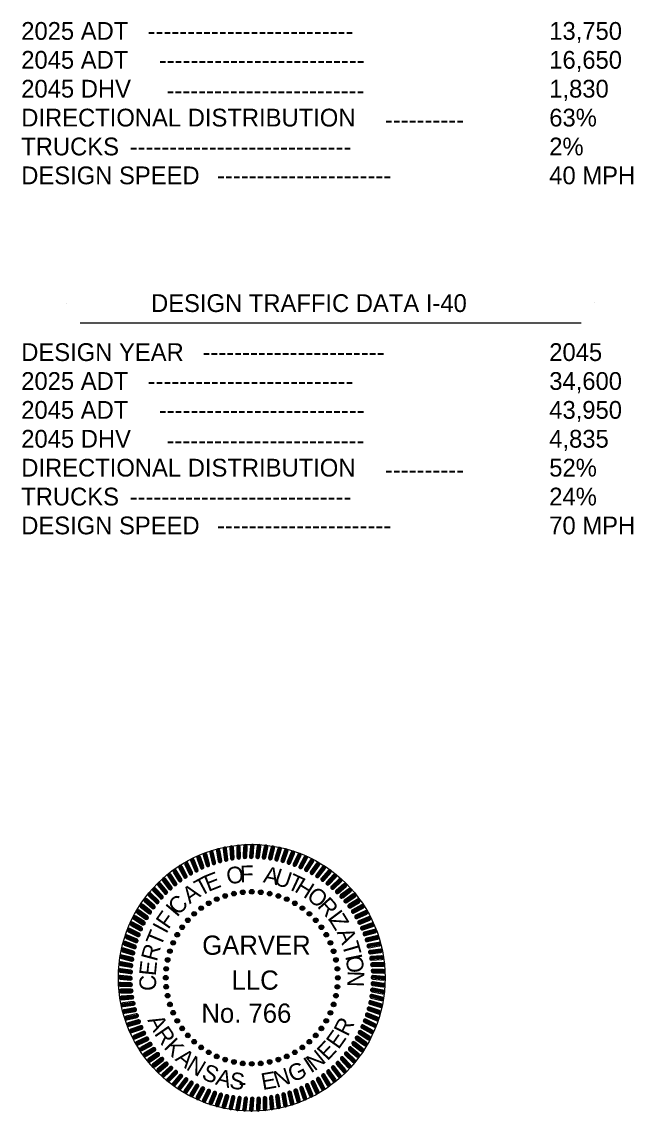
# Model space of a CAD drawing. Extents: x 535214 to 694517, y 381272 to 484355.
# Drawn here: x 658244 to 685754, y 383251 to 432276 of the extents above; entities that cross this region are included whole.
import ezdxf

# ---------------------------------------------------------------- set-up
doc = ezdxf.new("R2010")
doc.units = 0
for name, color, linetype in [('1', 7, 'Continuous'), ('2', 7, 'Continuous'), ('G-ANNO-STMP', 7, 'Continuous'), ('G-ANNO-TEXT', 7, 'Continuous')]:
    doc.layers.add(name, color=color, linetype=linetype)

# ---------------------------------------------------------------- blocks, each defined once
blk = doc.blocks.new('SEALDO')
at = {"layer": 'G-ANNO-TEXT'}
for radius in [0.0396, 0.0305, 0.0213, 0.0122, 0.00305]:
    blk.add_circle((1.403, -0.456), radius, dxfattribs=at)
blk = doc.blocks.new('SEALRI')
at = {"layer": 'G-ANNO-TEXT'}
for p, q in [((-0.023, 2.258), (-0.038, 2.081)), ((-0.008, 2.281), (-0.028, 2.056)), ((0.004, 2.286), (-0.016, 2.049)), ((0.016, 2.285), (-0.004, 2.048)), ((0.028, 2.278), (0.008, 2.052)), ((0.023, 2.076), (0.038, 2.253))]:
    blk.add_line(p, q, dxfattribs=at)
for centre, start, end in [((0.008, 2.256), 355, 175), ((-0.008, 2.078), 175, 355)]:
    blk.add_arc(centre, 0.0305, start, end, dxfattribs=at)

msp = doc.modelspace()

# ---------------------------------------------------------------- linework, layer by layer
at = {"layer": '1'}
for p, q in [((660254, 419616), (660254, 419616)), ((684029, 419646), (684029, 419646)), ((660875, 418727), (683419, 418727))]:
    msp.add_line(p, q, dxfattribs=at)
at = {"layer": 'G-ANNO-STMP'}
msp.add_circle((668592, 389255), 6000, dxfattribs=at)
msp.add_circle((668592, 389255), 6000, dxfattribs=at)

# ---------------------------------------------------------------- block references
for name, xscale, yscale, rotation in [('SEALRI', 2624.6202983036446, 2624.6202983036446, 12.000000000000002), ('SEALRI', 2624.6202983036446, 2624.6202983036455, 9), ('SEALRI', 2624.6202983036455, 2624.6202983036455, 6), ('SEALRI', 2624.620298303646, 2624.6202983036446, 3), ('SEALRI', 2624.6202983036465, 2624.620298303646, -2.999999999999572), ('SEALRI', 2624.620298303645, 2624.6202983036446, -5.9999999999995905), ('SEALRI', 2624.620298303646, 2624.6202983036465, -8.999999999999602), ('SEALRI', 2624.6202983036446, 2624.620298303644, -11.999999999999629), ('SEALRI', 2624.6202983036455, 2624.6202983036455, 26.999999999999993), ('SEALRI', 2624.6202983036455, 2624.6202983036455, 23.999999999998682), ('SEALRI', 2624.6202983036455, 2624.6202983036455, 20.999999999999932), ('SEALRI', 2624.6202983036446, 2624.6202983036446, 18), ('SEALRI', 2624.620298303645, 2624.620298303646, 15.000000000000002), ('SEALRI', 2624.620298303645, 2624.620298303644, -14.99999999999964), ('SEALRI', 2624.620298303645, 2624.620298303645, -17.999999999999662), ('SEALRI', 2624.620298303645, 2624.6202983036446, -20.999999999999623), ('SEALRI', 2624.620298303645, 2624.620298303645, -23.99999999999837), ('SEALRI', 2624.6202983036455, 2624.620298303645, -26.999999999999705), ('SEALRI', 2624.620298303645, 2624.6202983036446, 36), ('SEALRI', 2624.620298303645, 2624.6202983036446, 33), ('SEALRI', 2624.620298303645, 2624.6202983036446, 30.00000000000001), ('SEALRI', 2624.6202983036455, 2624.6202983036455, -29.99999999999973), ('SEALRI', 2624.6202983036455, 2624.620298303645, -32.999999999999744), ('SEALRI', 2624.620298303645, 2624.6202983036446, -35.999999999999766), ('SEALRI', 2624.6202983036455, 2624.6202983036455, 41.999999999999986), ('SEALRI', 2624.620298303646, 2624.620298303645, 38.999999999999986), ('SEALRI', 2624.620298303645, 2624.620298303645, -38.999999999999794), ('SEALRI', 2624.620298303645, 2624.620298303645, -41.99999999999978), ('SEALRI', 2624.6202983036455, 2624.6202983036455, 47.99999999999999), ('SEALRI', 2624.6202983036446, 2624.620298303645, 44.999999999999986), ('SEALDO', 2624.6202983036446, 2624.620298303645, 119.99999999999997), ('SEALDO', 2624.620298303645, 2624.6202983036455, 113.99999999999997), ('SEALDO', 2624.620298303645, 2624.620298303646, 107.99999999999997), ('SEALDO', 2624.620298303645, 2624.620298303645, 101.99999999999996), ('SEALRI', 2624.620298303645, 2624.620298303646, -44.99999999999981), ('SEALRI', 2624.6202983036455, 2624.6202983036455, -47.99999999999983), ('SEALRI', 2624.620298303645, 2624.6202983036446, 54), ('SEALRI', 2624.620298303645, 2624.620298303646, 51), ('SEALDO', 2624.620298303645, 2624.620298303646, 138), ('SEALDO', 2624.620298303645, 2624.6202983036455, 131.99999999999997), ('SEALDO', 2624.6202983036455, 2624.6202983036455, 125.99999999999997), ('SEALDO', 2624.6202983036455, 2624.6202983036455, 95.99999999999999), ('SEALDO', 2624.6202983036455, 2624.6202983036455, 90), ('SEALDO', 2624.6202983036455, 2624.620298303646, 83.99999999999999), ('SEALDO', 2624.6202983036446, 2624.620298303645, 77.99999999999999), ('SEALRI', 2624.620298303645, 2624.6202983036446, -50.999999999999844), ('SEALRI', 2624.620298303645, 2624.6202983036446, -53.999999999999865), ('SEALRI', 2624.6202983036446, 2624.6202983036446, 59.999999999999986), ('SEALRI', 2624.620298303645, 2624.620298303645, 56.99999999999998), ('SEALDO', 2624.620298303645, 2624.6202983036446, 150), ('SEALDO', 2624.6202983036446, 2624.620298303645, 144), ('SEALDO', 2624.6202983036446, 2624.620298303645, 72), ('SEALDO', 2624.6202983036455, 2624.6202983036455, 66.00000000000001), ('SEALRI', 2624.620298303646, 2624.620298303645, -56.999999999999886), ('SEALRI', 2624.620298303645, 2624.6202983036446, -59.99999999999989), ('SEALRI', 2624.620298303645, 2624.6202983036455, 65.99999999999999), ('SEALRI', 2624.6202983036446, 2624.6202983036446, 63), ('SEALDO', 2624.6202983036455, 2624.6202983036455, 156.00000000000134), ('SEALDO', 2624.620298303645, 2624.6202983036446, 60.00000000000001), ('SEALRI', 2624.6202983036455, 2624.6202983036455, -62.99999999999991), ('SEALRI', 2624.6202983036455, 2624.620298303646, -65.99999999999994), ('SEALRI', 2624.6202983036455, 2624.6202983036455, 68.99999999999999), ('SEALDO', 2624.620298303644, 2624.6202983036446, 168.00000000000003), ('SEALDO', 2624.6202983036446, 2624.620298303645, 162.00000000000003), ('SEALDO', 2624.620298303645, 2624.6202983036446, 54), ('SEALDO', 2624.6202983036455, 2624.6202983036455, 48.00000000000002), ('SEALRI', 2624.620298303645, 2624.6202983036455, -68.99999999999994), ('SEALRI', 2624.620298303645, 2624.620298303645, 75.00000000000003), ('SEALRI', 2624.6202983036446, 2624.620298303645, 72), ('SEALDO', 2624.6202983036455, 2624.6202983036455, 174.00000000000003), ('SEALDO', 2624.6202983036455, 2624.6202983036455, 42.000000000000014), ('SEALRI', 2624.620298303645, 2624.6202983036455, -71.99999999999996), ('SEALRI', 2624.6202983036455, 2624.6202983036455, -74.99999999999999), ('SEALRI', 2624.6202983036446, 2624.6202983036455, 81), ('SEALRI', 2624.6202983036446, 2624.6202983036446, 78.00000000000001), ('SEALDO', 2624.6202983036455, 2624.6202983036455, -179.99999999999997), ('SEALDO', 2624.620298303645, 2624.6202983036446, 36), ('SEALRI', 2624.6202983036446, 2624.6202983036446, -78), ('SEALRI', 2624.6202983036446, 2624.620298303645, -81.00000000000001), ('SEALRI', 2624.6202983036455, 2624.6202983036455, 84.00000000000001), ('SEALDO', 2624.6202983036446, 2624.620298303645, -167.99999999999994), ('SEALDO', 2624.620298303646, 2624.620298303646, -173.99999999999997), ('SEALDO', 2624.620298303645, 2624.6202983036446, 29.999999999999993), ('SEALDO', 2624.6202983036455, 2624.6202983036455, 23.999999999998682), ('SEALRI', 2624.6202983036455, 2624.6202983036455, -84.00000000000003), ('SEALRI', 2624.6202983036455, 2624.6202983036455, 90.00000000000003), ('SEALRI', 2624.620298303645, 2624.6202983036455, 87.00000000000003), ('SEALDO', 2624.620298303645, 2624.6202983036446, -161.9999999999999), ('SEALDO', 2624.6202983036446, 2624.6202983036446, 18), ('SEALRI', 2624.620298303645, 2624.6202983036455, -87.00000000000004), ('SEALRI', 2624.6202983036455, 2624.6202983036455, -90.00000000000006), ('SEALRI', 2624.620298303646, 2624.6202983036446, 93), ('SEALRI', 2624.6202983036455, 2624.620298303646, 96.00000000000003), ('SEALDO', 2624.620298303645, 2624.620298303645, -156.00000000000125), ('SEALDO', 2624.6202983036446, 2624.6202983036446, 12.000000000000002), ('SEALRI', 2624.620298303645, 2624.6202983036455, -96.0000000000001), ('SEALRI', 2624.620298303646, 2624.620298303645, -93.00000000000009), ('SEALRI', 2624.6202983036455, 2624.6202983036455, 99.00000000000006), ('SEALDO', 2624.620298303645, 2624.6202983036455, -149.99999999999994), ('SEALDO', 2624.6202983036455, 2624.6202983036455, 6), ('SEALRI', 2624.6202983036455, 2624.620298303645, -99.00000000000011), ('SEALRI', 2624.6202983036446, 2624.6202983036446, 102.00000000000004), ('SEALRI', 2624.6202983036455, 2624.6202983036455, 105.00000000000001), ('SEALDO', 2624.620298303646, 2624.620298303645, -143.99999999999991), ('SEALDO', 2624.6202983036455, 2624.6202983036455, -137.99999999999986), ('SEALDO', 2624.620298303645, 2624.6202983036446, -6.000000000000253), ('SEALRI', 2624.6202983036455, 2624.620298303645, -105.00000000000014), ('SEALRI', 2624.6202983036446, 2624.620298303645, -102.00000000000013), ('SEALRI', 2624.620298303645, 2624.620298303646, 108.00000000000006), ('SEALRI', 2624.6202983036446, 2624.620298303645, 111.00000000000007), ('SEALDO', 2624.6202983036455, 2624.6202983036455, -131.99999999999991), ('SEALDO', 2624.6202983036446, 2624.6202983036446, -12.000000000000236), ('SEALRI', 2624.6202983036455, 2624.6202983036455, -111.00000000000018), ('SEALRI', 2624.6202983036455, 2624.620298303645, -108.00000000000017), ('SEALRI', 2624.620298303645, 2624.620298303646, 114.00000000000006), ('SEALRI', 2624.620298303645, 2624.6202983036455, 117.00000000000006), ('SEALDO', 2624.6202983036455, 2624.620298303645, -125.9999999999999), ('SEALDO', 2624.620298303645, 2624.620298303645, -119.99999999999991), ('SEALDO', 2624.620298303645, 2624.620298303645, -18.000000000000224), ('SEALRI', 2624.6202983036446, 2624.6202983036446, -117.00000000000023), ('SEALRI', 2624.6202983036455, 2624.6202983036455, -114.0000000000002), ('SEALRI', 2624.6202983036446, 2624.620298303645, 120.00000000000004), ('SEALRI', 2624.620298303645, 2624.6202983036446, 123.00000000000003), ('SEALDO', 2624.6202983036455, 2624.6202983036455, -113.99999999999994), ('SEALDO', 2624.620298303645, 2624.6202983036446, -30.00000000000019), ('SEALDO', 2624.620298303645, 2624.6202983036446, -23.999999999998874), ('SEALRI', 2624.6202983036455, 2624.620298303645, -123.00000000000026), ('SEALRI', 2624.6202983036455, 2624.620298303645, -120.00000000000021), ('SEALRI', 2624.6202983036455, 2624.620298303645, 126.00000000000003), ('SEALRI', 2624.620298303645, 2624.620298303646, 129.00000000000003), ('SEALDO', 2624.620298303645, 2624.620298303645, -107.99999999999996), ('SEALDO', 2624.6202983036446, 2624.620298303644, -101.99999999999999), ('SEALDO', 2624.6202983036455, 2624.6202983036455, -96), ('SEALDO', 2624.620298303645, 2624.620298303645, -48.00000000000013), ('SEALDO', 2624.620298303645, 2624.6202983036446, -42.00000000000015), ('SEALDO', 2624.6202983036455, 2624.620298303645, -36.00000000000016), ('SEALRI', 2624.620298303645, 2624.620298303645, -129.00000000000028), ('SEALRI', 2624.620298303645, 2624.6202983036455, -126.00000000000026), ('SEALRI', 2624.620298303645, 2624.6202983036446, 132), ('SEALRI', 2624.620298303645, 2624.620298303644, 135), ('SEALDO', 2624.6202983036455, 2624.6202983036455, -90.00000000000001), ('SEALDO', 2624.6202983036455, 2624.6202983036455, -84.00000000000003), ('SEALDO', 2624.620298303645, 2624.620298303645, -78.00000000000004), ('SEALDO', 2624.620298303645, 2624.6202983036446, -72.00000000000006), ('SEALDO', 2624.620298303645, 2624.6202983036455, -66.00000000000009), ('SEALDO', 2624.620298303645, 2624.620298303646, -60.0000000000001), ('SEALDO', 2624.6202983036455, 2624.620298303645, -54.000000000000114), ('SEALRI', 2624.6202983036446, 2624.620298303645, -135.00000000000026), ('SEALRI', 2624.6202983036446, 2624.6202983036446, -132.00000000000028), ('SEALRI', 2624.620298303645, 2624.620298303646, 138), ('SEALRI', 2624.620298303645, 2624.6202983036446, 140.99999999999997), ('SEALRI', 2624.6202983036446, 2624.620298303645, 144), ('SEALRI', 2624.620298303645, 2624.6202983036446, -144.00000000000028), ('SEALRI', 2624.620298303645, 2624.620298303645, -141.0000000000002), ('SEALRI', 2624.620298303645, 2624.6202983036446, -138.00000000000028), ('SEALRI', 2624.620298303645, 2624.6202983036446, 146.99999999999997), ('SEALRI', 2624.620298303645, 2624.6202983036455, 149.99999999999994), ('SEALRI', 2624.6202983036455, 2624.6202983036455, 152.99999999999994), ('SEALRI', 2624.620298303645, 2624.6202983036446, 156.00000000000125), ('SEALRI', 2624.620298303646, 2624.620298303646, -156.00000000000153), ('SEALRI', 2624.620298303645, 2624.6202983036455, -153.00000000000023), ('SEALRI', 2624.6202983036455, 2624.6202983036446, -150.00000000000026), ('SEALRI', 2624.6202983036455, 2624.620298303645, -147.00000000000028), ('SEALRI', 2624.620298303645, 2624.6202983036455, 159), ('SEALRI', 2624.620298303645, 2624.6202983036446, 161.99999999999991), ('SEALRI', 2624.620298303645, 2624.620298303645, 164.99999999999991), ('SEALRI', 2624.6202983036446, 2624.6202983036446, 167.99999999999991), ('SEALRI', 2624.6202983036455, 2624.620298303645, 170.9999999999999), ('SEALRI', 2624.620298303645, 2624.6202983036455, 173.9999999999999), ('SEALRI', 2624.620298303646, 2624.620298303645, 176.9999999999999), ('SEALRI', 2624.6202983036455, 2624.6202983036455, 179.99999999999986), ('SEALRI', 2624.6202983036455, 2624.6202983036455, -177.00000000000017), ('SEALRI', 2624.620298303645, 2624.6202983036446, -174.00000000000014), ('SEALRI', 2624.6202983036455, 2624.6202983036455, -171.00000000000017), ('SEALRI', 2624.6202983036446, 2624.620298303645, -168.0000000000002), ('SEALRI', 2624.6202983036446, 2624.6202983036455, -165.0000000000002), ('SEALRI', 2624.6202983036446, 2624.6202983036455, -162.00000000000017), ('SEALRI', 2624.620298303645, 2624.6202983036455, -159.00000000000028)]:
    msp.add_blockref(name, (668592, 389255), dxfattribs=dict(at, xscale=xscale, yscale=yscale, rotation=rotation))
at = {"layer": 'G-ANNO-STMP', "xscale": 2624.6202983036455, "yscale": 2624.6202983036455}
for name in ['SEALRI', 'SEALDO']:
    msp.add_blockref(name, (668592, 389255), dxfattribs=at)

# ---------------------------------------------------------------- texts
at = {"layer": '1'}
msp.add_text('DESIGN TRAFFIC DATA I-40 ', height=800, dxfattribs=at).set_placement((664060, 419216))
at = {"layer": '2'}
for s, p in [('2025 ADT', (658220, 431464)), ('13,750', (681977, 431464)), (' --------------------------', (663608, 431464)), ('2045 ADT', (658220, 430164)), ('16,650', (681977, 430164)), ('--------------------------', (664408, 430164)), ('2045 DHV', (658220, 428864)), ('1,830', (681977, 428864)), ('-------------------------', (664756, 428797)), ('DIRECTIONAL DISTRIBUTION', (658220, 427564)), ('63%', (681977, 427564)), ('----------', (674582, 427475)), ('TRUCKS', (658220, 426264)), ('2%', (681977, 426264)), ('----------------------------', (663098, 426264)), ('DESIGN SPEED', (658220, 424964)), ('40 MPH', (681977, 424964)), ('----------------------', (667029, 424964)), ('DESIGN YEAR', (658220, 417011)), ('2045', (681977, 417011)), ('-----------------------', (666374, 417011)), ('2025 ADT', (658220, 415711)), ('34,600', (681977, 415711)), (' --------------------------', (663608, 415711)), ('2045 ADT', (658220, 414411)), ('--------------------------', (664408, 414411)), ('43,950', (681977, 414411)), ('2045 DHV', (658220, 413111)), ('4,835', (681977, 413111)), ('-------------------------', (664756, 413044)), ('DIRECTIONAL DISTRIBUTION', (658220, 411811)), ('52%', (681977, 411811)), ('----------', (674582, 411722)), ('TRUCKS', (658220, 410511)), ('24%', (681977, 410511)), ('----------------------------', (663098, 410511)), ('DESIGN SPEED', (658220, 409211)), ('70 MPH', (681977, 409211)), ('----------------------', (667029, 409211))]:
    msp.add_text(s, height=800, dxfattribs=at).set_placement(p)
at = {"layer": 'G-ANNO-STMP'}
for s, rotation, p in [('O', 8.2771, (667505, 393453)), ('F', 1.6104, (668074, 393550)), ('A', 348.2771, (669076, 393557)), ('U', 341.2772, (669545, 393482)), ('T', 28.2771, (666274, 392903)), ('E', 21.6104, (666637, 393115)), ('T', 334.9438, (670135, 393292)), ('H', 328.2771, (670472, 393158)), ('A', 34.9438, (665797, 392558)), ('O', 319.7874, (671015, 392850)), ('C', 44.3881, (665266, 392029)), ('R', 311.9933, (671507, 392457)), ('F', 54.9438, (664837, 391403)), ('I', 49.7408, (665227, 391952)), ('I', 307.0081, (671964, 391943)), ('I', 61.6104, (664748, 391200)), ('Z', 301.6104, (672053, 391853)), ('T', 67.4314, (664496, 390619)), ('A', 292.9752, (672406, 391308)), ('R', 74.9438, (664320, 389959)), ('T', 286.3085, (672641, 390765)), ('I', 281.6104, (672791, 390238)), ('E', 83.8985, (664266, 389317)), ('O', 276.4823, (672820, 390211)), ('C', 91.8842, (664300, 388677)), ('N', 268.2771, (672914, 389578)), ('A', 296.5747, (663883, 387355)), ('R', 63.0959, (672913, 386577)), ('R', 304.6183, (664179, 386738)), ('E', 54.7309, (672495, 386001)), ('K', 313.3805, (664601, 386110)), ('E', 46.6807, (671999, 385489)), ('A', 321.2584, (665108, 385562)), ('N', 38.9821, (671419, 385031)), ('N', 329.1099, (665601, 385147)), ('S', 337.6294, (666293, 384725)), ('G', 26.4132, (670449, 384524)), ('I', 32.979, (671245, 384942)), ('A', 345.4073, (666924, 384460)), ('S', 352.8046, (667560, 384281)), ('E', 10.0695, (669083, 384201)), ('N', 17.8686, (669710, 384294)), ('-', 0.8385, (668013, 384184))]:
    msp.add_text(s, height=750, rotation=rotation, dxfattribs=at).set_placement(p)
for s, p in [('GARVER', (666363, 390291)), ('LLC', (667684, 388720)), ('No. 766', (666325, 387233))]:
    msp.add_text(s, height=864, dxfattribs=at).set_placement(p)

doc.saveas('drawing.dxf')
